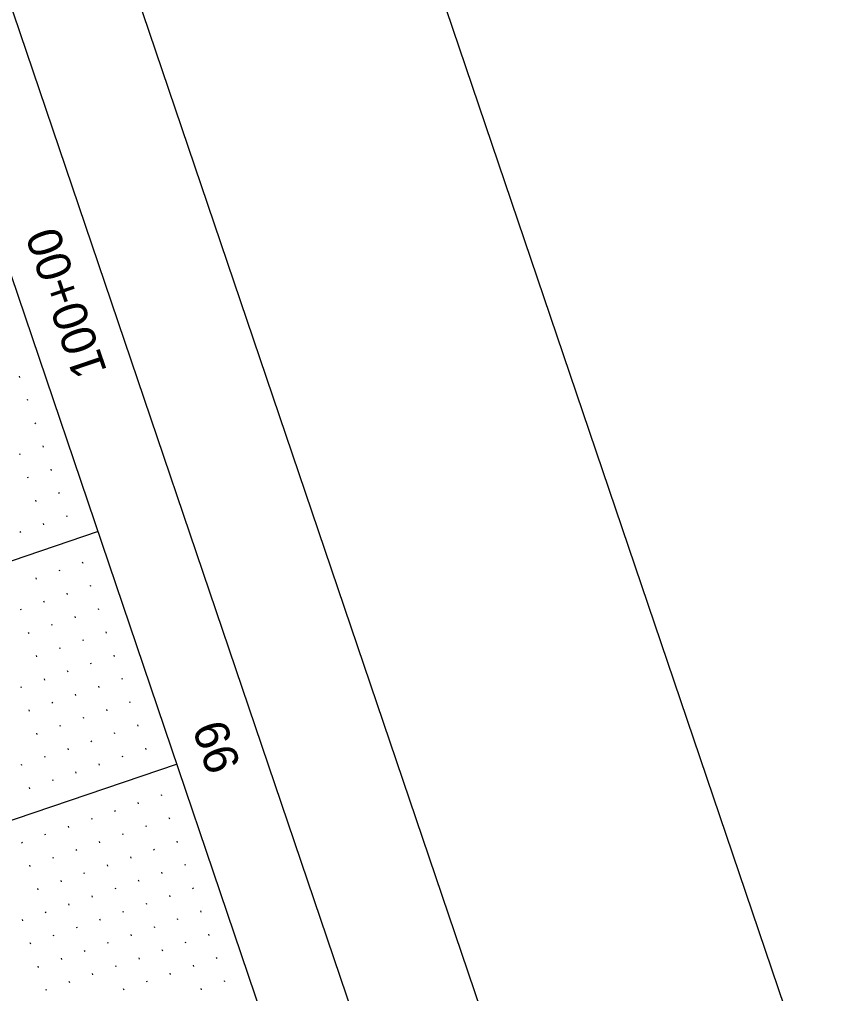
# Model space of a CAD drawing. Extents: x 2150318 to 2152065, y 143281 to 145371.
# Drawn here: x 2151482.1 to 2151649.1, y 144834 to 145032.3 of the extents above; entities that cross this region are included whole.
import ezdxf

# ---------------------------------------------------------------- set-up
doc = ezdxf.new("R2010")
doc.units = 0
for name, color, linetype in [('SHT_Plan_Profile_Sheet_Sta_Txt', 7, 'Continuous'), ('SHT_Plot_Shape_Full', 7, 'Continuous'), ('SHT_Plot_Shape_Half', 7, 'Continuous'), ('SHT_Profile_Grid_Major', 7, 'Continuous'), ('SHT_Profile_Grid_Minor', 7, 'Continuous'), ('SHT_Sheet_Border', 7, 'Continuous')]:
    doc.layers.add(name, color=color, linetype=linetype)

msp = doc.modelspace()

# ---------------------------------------------------------------- linework, layer by layer
at = {"layer": 'SHT_Plot_Shape_Full'}
msp.add_lwpolyline([(2150896.74, 143280.62), (2150318.46, 144985.2), (2151454.85, 145370.71), (2152033.12, 143666.13)], close=True, dxfattribs=at)
at = {"layer": 'SHT_Plot_Shape_Half'}
msp.add_lwpolyline([(2150909.49, 143371.4), (2150363.35, 144981.29), (2151405.04, 145334.68), (2151951.18, 143724.79)], close=True, dxfattribs=at)
at = {"layer": 'SHT_Profile_Grid_Major'}
for p, q in [((2151498.11, 144928.02), (2151024.62, 144767.39)), ((2151514.18, 144880.67), (2151085.63, 144735.29))]:
    msp.add_line(p, q, dxfattribs=at)
at = {"layer": 'SHT_Profile_Grid_Minor'}
for p, q in [((2151482.17, 144959.44), (2151482.09, 144959.68)), ((2151483.78, 144954.71), (2151483.7, 144954.94)), ((2151485.39, 144949.97), (2151485.31, 144950.21)), ((2151486.99, 144945.24), (2151486.91, 144945.47)), ((2151482.26, 144943.63), (2151482.18, 144943.87)), ((2151488.6, 144940.5), (2151488.52, 144940.74)), ((2151483.86, 144938.89), (2151483.78, 144939.13)), ((2151485.47, 144934.16), (2151485.39, 144934.4)), ((2151490.21, 144935.77), (2151490.13, 144936)), ((2151491.81, 144931.03), (2151491.73, 144931.27)), ((2151487.08, 144929.42), (2151487, 144929.66)), ((2151482.34, 144927.82), (2151482.26, 144928.06)), ((2151495.03, 144921.56), (2151494.94, 144921.8)), ((2151485.56, 144918.35), (2151485.47, 144918.59)), ((2151490.29, 144919.95), (2151490.21, 144920.19)), ((2151496.63, 144916.83), (2151496.55, 144917.06)), ((2151491.9, 144915.22), (2151491.82, 144915.46)), ((2151487.16, 144913.61), (2151487.08, 144913.85)), ((2151482.43, 144912.01), (2151482.35, 144912.24)), ((2151493.5, 144910.49), (2151493.42, 144910.72)), ((2151498.24, 144912.09), (2151498.16, 144912.33)), ((2151488.77, 144908.88), (2151488.69, 144909.12)), ((2151484.03, 144907.27), (2151483.95, 144907.51)), ((2151499.84, 144907.36), (2151499.76, 144907.59)), ((2151495.11, 144905.75), (2151495.03, 144905.99)), ((2151485.64, 144902.54), (2151485.56, 144902.77)), ((2151490.37, 144904.14), (2151490.29, 144904.38)), ((2151501.45, 144902.62), (2151501.37, 144902.86)), ((2151496.72, 144901.02), (2151496.64, 144901.25)), ((2151491.98, 144899.41), (2151491.9, 144899.65)), ((2151487.25, 144897.8), (2151487.17, 144898.04)), ((2151503.06, 144897.89), (2151502.98, 144898.12)), ((2151482.51, 144896.2), (2151482.43, 144896.43)), ((2151493.59, 144894.67), (2151493.51, 144894.91)), ((2151498.32, 144896.28), (2151498.24, 144896.52)), ((2151488.85, 144893.07), (2151488.77, 144893.3)), ((2151504.66, 144893.15), (2151504.58, 144893.39)), ((2151484.12, 144891.46), (2151484.04, 144891.7)), ((2151499.93, 144891.55), (2151499.85, 144891.78)), ((2151495.19, 144889.94), (2151495.11, 144890.18)), ((2151485.72, 144886.73), (2151485.64, 144886.96)), ((2151490.46, 144888.33), (2151490.38, 144888.57)), ((2151501.53, 144886.81), (2151501.45, 144887.05)), ((2151506.27, 144888.42), (2151506.19, 144888.65)), ((2151496.8, 144885.2), (2151496.72, 144885.44)), ((2151492.06, 144883.6), (2151491.98, 144883.83)), ((2151507.88, 144883.68), (2151507.8, 144883.92)), ((2151487.33, 144881.99), (2151487.25, 144882.23)), ((2151503.14, 144882.08), (2151503.06, 144882.31)), ((2151482.59, 144880.39), (2151482.51, 144880.62)), ((2151493.67, 144878.86), (2151493.59, 144879.1)), ((2151498.41, 144880.47), (2151498.33, 144880.71)), ((2151488.94, 144877.26), (2151488.86, 144877.49)), ((2151484.2, 144875.65), (2151484.12, 144875.89)), ((2151511.09, 144874.21), (2151511.01, 144874.45)), ((2151501.62, 144871), (2151501.54, 144871.24)), ((2151506.35, 144872.61), (2151506.27, 144872.84)), ((2151496.88, 144869.39), (2151496.8, 144869.63)), ((2151512.69, 144869.48), (2151512.61, 144869.71)), ((2151492.15, 144867.79), (2151492.07, 144868.02)), ((2151507.96, 144867.87), (2151507.88, 144868.11)), ((2151487.41, 144866.18), (2151487.33, 144866.42)), ((2151503.22, 144866.26), (2151503.14, 144866.5)), ((2151514.3, 144864.74), (2151514.22, 144864.98)), ((2151482.68, 144864.57), (2151482.6, 144864.81)), ((2151493.75, 144863.05), (2151493.67, 144863.29)), ((2151498.49, 144864.66), (2151498.41, 144864.89)), ((2151509.57, 144863.14), (2151509.49, 144863.37)), ((2151489.02, 144861.45), (2151488.94, 144861.68)), ((2151504.83, 144861.53), (2151504.75, 144861.77)), ((2151484.28, 144859.84), (2151484.2, 144860.08)), ((2151500.1, 144859.92), (2151500.02, 144860.16)), ((2151515.91, 144860.01), (2151515.83, 144860.24)), ((2151495.36, 144858.32), (2151495.28, 144858.55)), ((2151506.44, 144856.79), (2151506.36, 144857.03)), ((2151511.17, 144858.4), (2151511.09, 144858.64)), ((2151485.89, 144855.1), (2151485.81, 144855.34)), ((2151490.63, 144856.71), (2151490.55, 144856.95)), ((2151501.7, 144855.19), (2151501.62, 144855.42)), ((2151517.51, 144855.27), (2151517.43, 144855.51)), ((2151496.97, 144853.58), (2151496.89, 144853.82)), ((2151512.78, 144853.67), (2151512.7, 144853.9)), ((2151492.23, 144851.98), (2151492.15, 144852.21)), ((2151508.04, 144852.06), (2151507.96, 144852.3)), ((2151487.5, 144850.37), (2151487.42, 144850.61)), ((2151498.57, 144848.85), (2151498.49, 144849.08)), ((2151503.31, 144850.45), (2151503.23, 144850.69)), ((2151514.38, 144848.93), (2151514.3, 144849.17)), ((2151519.12, 144850.54), (2151519.04, 144850.77)), ((2151482.76, 144848.76), (2151482.68, 144849)), ((2151493.84, 144847.24), (2151493.76, 144847.48)), ((2151509.65, 144847.32), (2151509.57, 144847.56)), ((2151489.1, 144845.63), (2151489.02, 144845.87)), ((2151504.91, 144845.72), (2151504.83, 144845.95)), ((2151520.73, 144845.8), (2151520.65, 144846.04)), ((2151484.37, 144844.03), (2151484.29, 144844.26)), ((2151500.18, 144844.11), (2151500.1, 144844.35)), ((2151515.99, 144844.2), (2151515.91, 144844.43)), ((2151490.71, 144840.9), (2151490.63, 144841.14)), ((2151495.45, 144842.51), (2151495.36, 144842.74)), ((2151506.52, 144840.98), (2151506.44, 144841.22)), ((2151511.26, 144842.59), (2151511.18, 144842.83)), ((2151522.33, 144841.07), (2151522.25, 144841.3)), ((2151485.98, 144839.29), (2151485.89, 144839.53)), ((2151501.79, 144839.38), (2151501.71, 144839.61)), ((2151517.6, 144839.46), (2151517.52, 144839.7)), ((2151497.05, 144837.77), (2151496.97, 144838.01)), ((2151512.86, 144837.85), (2151512.78, 144838.09)), ((2151492.32, 144836.16), (2151492.24, 144836.4)), ((2151508.13, 144836.25), (2151508.05, 144836.48)), ((2151523.94, 144836.33), (2151523.86, 144836.57)), ((2151487.58, 144834.56), (2151487.5, 144834.79)), ((2151503.39, 144834.64), (2151503.31, 144834.88)), ((2151519.2, 144834.73), (2151519.12, 144834.96))]:
    msp.add_line(p, q, dxfattribs=at)
at = {"layer": 'SHT_Sheet_Border'}
msp.add_line((2151879.61, 143803.47), (2151457.96, 145046.39), dxfattribs=at)
msp.add_lwpolyline([(2150901.85, 143471.77), (2150395.86, 144963.28), (2151390.2, 145300.6), (2151896.19, 143809.09)], close=True, dxfattribs=at)

# ---------------------------------------------------------------- texts
at = {"layer": 'SHT_Plan_Profile_Sheet_Sta_Txt'}
for s, p in [('100+00', (2151499.96, 144960.72)), ('99', (2151527.21, 144880.38))]:
    msp.add_text(s, height=7, rotation=108.7393, dxfattribs=at).set_placement(p)

doc.saveas('drawing.dxf')
